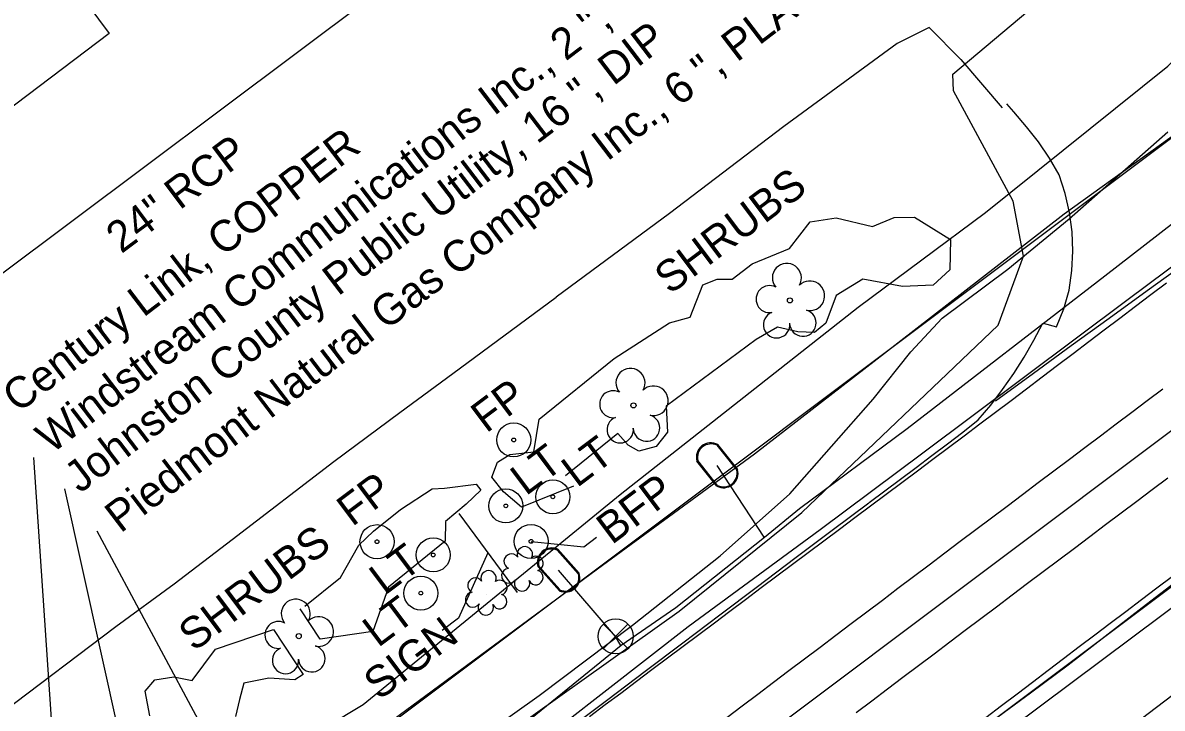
# Model space of a CAD drawing. Extents: x 2186615 to 2188822, y 629899 to 631820.
# Drawn here: x 2188283 to 2188429.1, y 631312.5 to 631400.3 of the extents above; entities that cross this region are included whole.
import ezdxf

# ---------------------------------------------------------------- set-up
doc = ezdxf.new("R2010")
doc.units = 0
for name, color, linetype in [('Exist Building Metal Canopy', 7, 'Continuous'), ('Exist Horizontal Alignment', 7, 'Continuous'), ('Exist Other Culture Located Object CELL', 7, 'Continuous'), ('Exist Other Culture Located Object Text', 7, 'Continuous'), ('Exist Other Culture Sign', 7, 'Continuous'), ('Exist Other Culture Sign Leader', 7, 'Continuous'), ('Exist Other Culture Sign Text', 7, 'Continuous'), ('Exist Right of Way Line', 7, 'Continuous'), ('Exist Roads EOP', 7, 'Continuous'), ('Exist Roads EOP Other', 7, 'Continuous'), ('Exist Roads EOT', 7, 'Continuous'), ('Exist Structure Minor Pipes RCP 24 Inch', 7, 'Continuous'), ('Exist Structure Minor Pipes RCP 24 Inch Text', 7, 'Continuous'), ('Exist Utilities Gas UG Line SUE LOS B', 7, 'Continuous'), ('Exist Utilities Gas UG Line SUE LOS B Leader', 7, 'Continuous'), ('Exist Utilities Gas UG Line SUE LOS B Text', 7, 'Continuous'), ('Exist Utilities Other Located Object CELL', 7, 'Continuous'), ('Exist Utilities Other Located Object Leader', 7, 'Continuous'), ('Exist Utilities Other Located Object Text', 7, 'Continuous'), ('Exist Utilities Sanitary Sewer Forced Main SUE LOS B', 7, 'Continuous'), ('Exist Utilities Telephone UG Cable SUE LOS C', 7, 'Continuous'), ('Exist Utilities Telephone UG Cable SUE LOS C Text', 7, 'Continuous'), ('Exist Utilities Telephone UG FO SUE LOS B', 7, 'Continuous'), ('Exist Utilities Telephone UG FO SUE LOS B Leader', 7, 'Continuous'), ('Exist Utilities Telephone UG FO SUE LOS B Text', 7, 'Continuous'), ('Exist Utilities Water Meter CELL', 7, 'Continuous'), ('Exist Utilities Water UG Line SUE LOS B', 7, 'Continuous'), ('Exist Utilities Water UG Line SUE LOS B Leader', 7, 'Continuous'), ('Exist Utilities Water UG Line SUE LOS B Text', 7, 'Continuous'), ('Exist Utilities Water Valve CELL', 7, 'Continuous'), ('Exist Vegetation Hedge Row', 7, 'Continuous'), ('Exist Vegetation Hedge Row Text', 7, 'Continuous'), ('Exist Vegetation Shrub CELL', 7, 'Continuous'), ('Exist Vegetation Tree CELL', 7, 'Continuous')]:
    doc.layers.add(name, color=color, linetype=linetype)

msp = doc.modelspace()

# ---------------------------------------------------------------- linework, layer by layer
at = {"layer": 'Exist Building Metal Canopy'}
msp.add_lwpolyline([(2188283.33, 631413.53), (2188294.13, 631398.96), (2188250.61, 631366.09), (2188239.7, 631380.77)], dxfattribs=at)
at = {"layer": 'Exist Horizontal Alignment'}
msp.add_line((2187136.41, 630378.11), (2188520.86, 631416.04), dxfattribs=at)
at = {"layer": 'Exist Other Culture Located Object CELL'}
for centre, radius in [((2188345.97, 631346.9), 2.18), ((2188345.97, 631346.9), 0.24), ((2188328.45, 631333.87), 2.18), ((2188328.45, 631333.87), 0.24)]:
    msp.add_circle(centre, radius, dxfattribs=at)
at = {"layer": 'Exist Other Culture Sign'}
msp.add_line((2188338.92, 631337.5), (2188346.41, 631327.34), dxfattribs=at)
at = {"layer": 'Exist Other Culture Sign Leader'}
msp.add_lwpolyline([(2188342.67, 631332.42), (2188338.9, 631324.06), (2188336.82, 631322.5)], dxfattribs=at)
at = {"layer": 'Exist Right of Way Line'}
msp.add_line((2187118.41, 630402.11), (2188502.83, 631440.02), dxfattribs=at)
at = {"layer": 'Exist Roads EOP'}
msp.add_line((2188413.82, 631361.87), (2188415.52, 631361.39), dxfattribs=at)
for points in [[(2188407.73, 631351.93), (2188412.58, 631355.47), (2188417.43, 631359), (2188422.29, 631362.52), (2188427.16, 631366.03), (2188432.02, 631369.54), (2188436.84, 631373.11), (2188441.63, 631376.72), (2188446.43, 631380.33), (2188451.22, 631383.93), (2188456.02, 631387.53), (2188460.83, 631391.12), (2188465.64, 631394.71), (2188470.43, 631398.33), (2188475.18, 631402), (2188479.55, 631405.46)], [(2188415.55, 631361.39), (2188416.47, 631363.71), (2188417.16, 631366.11), (2188417.51, 631368.59), (2188417.63, 631371.08), (2188417.54, 631373.58), (2188417.21, 631376.06), (2188416.66, 631378.49), (2188415.88, 631380.85), (2188414.66, 631383.02), (2188413.25, 631385.08), (2188411.71, 631387.03), (2188410.09, 631388.92), (2188409.16, 631389.97)], [(2188391.55, 631338.9), (2188393.55, 631340.39), (2188395.55, 631341.89), (2188397.55, 631343.39), (2188399.55, 631344.9), (2188401.55, 631346.4), (2188403.53, 631347.92), (2188405.48, 631349.5), (2188407.13, 631351.37), (2188408.64, 631353.36), (2188410.08, 631355.41), (2188411.41, 631357.52), (2188412.65, 631359.69), (2188413.79, 631361.88)], [(2188281.29, 631256.01), (2188286.1, 631259.61), (2188290.9, 631263.21), (2188295.7, 631266.81), (2188300.49, 631270.41), (2188305.29, 631274.01), (2188310.09, 631277.62), (2188314.89, 631281.22), (2188319.68, 631284.82), (2188324.48, 631288.43), (2188329.28, 631292.03), (2188334.08, 631295.63), (2188338.87, 631299.24), (2188343.67, 631302.84), (2188348.47, 631306.45), (2188353.26, 631310.05), (2188358.05, 631313.67), (2188362.84, 631317.28), (2188367.63, 631320.9), (2188372.41, 631324.51), (2188377.2, 631328.13), (2188381.99, 631331.74), (2188386.8, 631335.34), (2188391.5, 631338.86)], [(2188431.29, 631329.05), (2188426.54, 631325.39), (2188421.79, 631321.72), (2188417.03, 631318.07), (2188412.22, 631314.48), (2188407.4, 631310.9)]]:
    msp.add_lwpolyline(points, dxfattribs=at)
at = {"layer": 'Exist Roads EOP Other'}
for points in [[(2188399.23, 631399.74), (2188395.12, 631397.69), (2188380.6, 631387.04), (2188365.94, 631375.92), (2188351.43, 631365.2)], [(2188399.23, 631399.74), (2188403.26, 631395.66), (2188408.58, 631389.47)], [(2188185.7, 631240.3), (2188187.96, 631243.01), (2188193.78, 631247.53), (2188201.43, 631253.2), (2188215.32, 631263.49), (2188232.85, 631276.89), (2188243.59, 631284.88), (2188251.81, 631290.7), (2188259.11, 631296.15), (2188265.42, 631301.04), (2188273.98, 631307.19), (2188280.4, 631311.98), (2188294.99, 631323), (2188302.46, 631328.46), (2188309.89, 631334.14), (2188322.91, 631344.13), (2188331.39, 631350.42), (2188338.16, 631355.42), (2188351.43, 631365.2)]]:
    msp.add_lwpolyline(points, dxfattribs=at)
at = {"layer": 'Exist Roads EOT'}
for points in [[(2188355.69, 631311.49), (2188357.69, 631312.99), (2188359.69, 631314.48), (2188361.69, 631315.98), (2188363.69, 631317.48), (2188365.69, 631318.98), (2188367.69, 631320.48), (2188369.69, 631321.98), (2188371.69, 631323.48), (2188373.69, 631324.98), (2188375.69, 631326.48), (2188377.7, 631327.98), (2188379.7, 631329.48), (2188381.7, 631330.97), (2188383.7, 631332.47), (2188385.7, 631333.97), (2188387.71, 631335.47), (2188389.71, 631336.96), (2188391.71, 631338.46), (2188393.71, 631339.96), (2188395.71, 631341.46), (2188397.71, 631342.96), (2188399.71, 631344.45), (2188401.71, 631345.95), (2188403.71, 631347.45), (2188405.71, 631348.95), (2188407.71, 631350.45), (2188409.71, 631351.96), (2188411.7, 631353.47), (2188413.7, 631354.97), (2188415.69, 631356.48), (2188417.69, 631357.99), (2188419.68, 631359.5), (2188421.67, 631361.01), (2188423.67, 631362.51), (2188425.66, 631364.02), (2188427.65, 631365.53), (2188429.65, 631367.04)], [(2188373.27, 631311.34), (2188375.26, 631312.84), (2188377.26, 631314.35), (2188379.26, 631315.86), (2188381.25, 631317.36), (2188383.25, 631318.87), (2188385.24, 631320.37), (2188387.24, 631321.88), (2188389.24, 631323.38), (2188391.23, 631324.89), (2188393.23, 631326.39), (2188395.22, 631327.9), (2188397.22, 631329.4), (2188399.21, 631330.91), (2188401.21, 631332.42), (2188403.21, 631333.92), (2188405.2, 631335.42), (2188407.2, 631336.93), (2188409.2, 631338.43), (2188411.2, 631339.93), (2188413.19, 631341.44), (2188415.19, 631342.94), (2188417.19, 631344.44), (2188419.19, 631345.95), (2188421.18, 631347.45), (2188423.18, 631348.95), (2188425.18, 631350.46), (2188427.18, 631351.96), (2188429.17, 631353.46)], [(2188389.88, 631311.99), (2188391.87, 631313.49), (2188393.87, 631315), (2188395.86, 631316.51), (2188397.86, 631318.01), (2188399.86, 631319.52), (2188401.85, 631321.02), (2188403.85, 631322.53), (2188405.85, 631324.03), (2188407.84, 631325.53), (2188409.84, 631327.04), (2188411.84, 631328.54), (2188413.84, 631330.04), (2188415.83, 631331.55), (2188417.83, 631333.05), (2188419.83, 631334.55), (2188421.83, 631336.06), (2188423.82, 631337.56), (2188425.82, 631339.06), (2188427.82, 631340.57), (2188429.82, 631342.07)], [(2188430.42, 631329.42), (2188428.42, 631327.91), (2188426.43, 631326.41), (2188424.43, 631324.9), (2188422.43, 631323.39), (2188420.44, 631321.89), (2188418.45, 631320.38), (2188416.45, 631318.87), (2188414.46, 631317.36), (2188412.47, 631315.85), (2188410.48, 631314.34), (2188408.48, 631312.83), (2188406.49, 631311.32)]]:
    msp.add_lwpolyline(points, dxfattribs=at)
at = {"layer": 'Exist Structure Minor Pipes RCP 24 Inch'}
msp.add_line((2188121.59, 631249.35), (2188427.77, 631478.57), dxfattribs=at)
at = {"layer": 'Exist Utilities Gas UG Line SUE LOS B'}
msp.add_lwpolyline([(2188219.39, 631219.84), (2188231.62, 631228.2), (2188246.17, 631238.93), (2188255.42, 631245.33), (2188268.48, 631254.78), (2188278.59, 631262.16), (2188293.89, 631272.96), (2188309.4, 631283.84), (2188325.21, 631295.95), (2188338.4, 631306.43), (2188349.22, 631314.15), (2188361.2, 631323.18), (2188372.45, 631332.07), (2188381.36, 631339.98), (2188392.05, 631352.12), (2188396.89, 631358.2), (2188400.9, 631362.5), (2188409.32, 631368.76), (2188417.18, 631375.21), (2188429.81, 631386.38)], dxfattribs=at)
at = {"layer": 'Exist Utilities Gas UG Line SUE LOS B Leader'}
msp.add_line((2188316.89, 631289.98), (2188292.6, 631335.2), dxfattribs=at)
at = {"layer": 'Exist Utilities Other Located Object CELL'}
for centre, radius in [((2188350.99, 631339.62), 2.18), ((2188344.96, 631338.45), 2.18), ((2188350.99, 631339.62), 0.24), ((2188344.96, 631338.45), 0.24), ((2188348.19, 631333.91), 2.18), ((2188335.66, 631332.17), 2.18), ((2188348.19, 631333.91), 0.24), ((2188335.66, 631332.17), 0.24), ((2188334.07, 631327.28), 2.18), ((2188334.07, 631327.28), 0.24)]:
    msp.add_circle(centre, radius, dxfattribs=at)
at = {"layer": 'Exist Utilities Other Located Object Leader'}
msp.add_lwpolyline([(2188348.19, 631333.91), (2188354.95, 631333.21), (2188356.57, 631334.43)], dxfattribs=at)
at = {"layer": 'Exist Utilities Sanitary Sewer Forced Main SUE LOS B'}
msp.add_lwpolyline([(2188052.08, 631035.89), (2188074.5, 631052.61), (2188093.79, 631066.37), (2188121.43, 631086.62), (2188146.17, 631105.29), (2188183, 631130.32), (2188212.25, 631151.9), (2188236.06, 631169.55), (2188274.9, 631197.79), (2188300.59, 631215.98), (2188344.72, 631249.04), (2188387.13, 631281.33), (2188437.44, 631319.58), (2188480.75, 631351.94), (2188530.77, 631388.8), (2188537.37, 631394.07)], dxfattribs=at)
at = {"layer": 'Exist Utilities Telephone UG Cable SUE LOS C'}
for points in [[(2188408.07, 631361.6), (2188411.32, 631370.46), (2188409.98, 631377.49), (2188402.34, 631391.62), (2188402.24, 631393.77), (2188411.88, 631401.83), (2188434.34, 631422.63), (2188440.61, 631427.17), (2188442.76, 631427.28), (2188447.4, 631424.9), (2188452.58, 631419.05), (2188455.8, 631415.11), (2188458.95, 631413.82), (2188466.14, 631418.76)], [(2188359.63, 631339.91), (2188390.14, 631363.91), (2188406.42, 631376.04), (2188429.82, 631394.77), (2188450.5, 631414.66)], [(2188096.88, 630993.34), (2188080.22, 631017.51), (2188064.37, 631042.87), (2188062.98, 631045.24), (2188062.65, 631047.71), (2188067.09, 631054.3), (2188068.63, 631056.84), (2188089.09, 631072.74), (2188116.44, 631092.81), (2188141.03, 631110.94), (2188178.22, 631138.01), (2188229.96, 631175.9), (2188269.4, 631205.59), (2188294.58, 631224.2), (2188340.11, 631258.2), (2188382.72, 631289.85), (2188432.93, 631327.36), (2188477.32, 631360.56), (2188524.82, 631398.08), (2188530.94, 631402.62)], [(2188239.88, 631089.23), (2188209.7, 631139.17), (2188205.31, 631145.33), (2188202.92, 631147.6), (2188200.81, 631153.01), (2188202.37, 631156.1), (2188209.69, 631162.82), (2188228.85, 631177.06), (2188268.68, 631206.68), (2188293.54, 631225.66), (2188339.11, 631259.48), (2188381.57, 631291.6), (2188431.82, 631329.3), (2188475.74, 631362.76), (2188523.99, 631399.21), (2188530.06, 631403.8)], [(2188312.37, 631280.51), (2188341.87, 631302.43), (2188368.35, 631323.01), (2188385.25, 631335.41), (2188398.42, 631345.26), (2188424.55, 631364.83), (2188476.35, 631403.47)], [(2188310.34, 631283.34), (2188339.41, 631305.19), (2188367.17, 631324.97), (2188382.91, 631337.59), (2188408.07, 631361.6)], [(2188214.19, 631233.71), (2188214.21, 631236.64), (2188215.1, 631239.68), (2188225.32, 631247.53), (2188241.06, 631256.41), (2188259.35, 631266.95), (2188283.55, 631284.49), (2188303.17, 631298.86), (2188326.67, 631313), (2188359.63, 631339.91)]]:
    msp.add_lwpolyline(points, dxfattribs=at)
at = {"layer": 'Exist Utilities Telephone UG FO SUE LOS B'}
msp.add_lwpolyline([(2188303.07, 631290.83), (2188335.53, 631314.77), (2188356.73, 631330.39), (2188376.84, 631345.11), (2188395.22, 631359.35), (2188416.54, 631375.89), (2188457.16, 631405.12)], dxfattribs=at)
at = {"layer": 'Exist Utilities Telephone UG FO SUE LOS B Leader'}
msp.add_line((2188288.8, 631280.26), (2188284.46, 631344.66), dxfattribs=at)
at = {"layer": 'Exist Utilities Water Meter CELL'}
for p, q in [((2188372.06, 631343.65), (2188372.06, 631343.65)), ((2188351.73, 631330.24), (2188351.73, 631330.24))]:
    msp.add_line(p, q, dxfattribs=at)
for points in [[(2188372.01, 631346.22), (2188374.55, 631343.03)], [(2188372.11, 631346.3), (2188374.66, 631343.12)], [(2188372, 631341), (2188369.44, 631344.2)], [(2188372.11, 631341.08), (2188369.55, 631344.29)], [(2188351.54, 631332.8), (2188354.25, 631329.76)], [(2188351.64, 631332.89), (2188354.35, 631329.85)], [(2188351.82, 631327.59), (2188349.09, 631330.65)], [(2188351.92, 631327.68), (2188349.19, 631330.74)]]:
    msp.add_lwpolyline(points, dxfattribs=at)
for centre, radius, start, end in [((2188371.24, 631344.67), 1.86, 61.8182, 194.6196), ((2188371.25, 631344.66), 1.73, 63.9411, 192.4226), ((2188372.87, 631342.64), 1.86, 242.2885, 14.9486), ((2188372.87, 631342.63), 1.73, 243.7674, 13.513), ((2188350.85, 631331.21), 1.86, 64.9405, 197.7419), ((2188350.86, 631331.2), 1.73, 67.0634, 195.5449), ((2188352.59, 631329.28), 1.86, 245.4108, 18.0709), ((2188352.6, 631329.27), 1.73, 246.8897, 16.6353)]:
    msp.add_arc(centre, radius, start, end, dxfattribs=at)
at = {"layer": 'Exist Utilities Water UG Line SUE LOS B'}
msp.add_line((2188378.09, 631334.43), (2188372.06, 631343.65), dxfattribs=at)
for points in [[(2188311.2, 631281.93), (2188339.94, 631304.52), (2188359.74, 631320.63), (2188366.75, 631325.42), (2188378.12, 631334.45), (2188382.61, 631338.14), (2188396.4, 631348.39), (2188421.73, 631367.94), (2188462.18, 631399.29)], [(2188359.7, 631320.59), (2188359.03, 631321.73), (2188351.73, 631330.24)]]:
    msp.add_lwpolyline(points, dxfattribs=at)
at = {"layer": 'Exist Utilities Water UG Line SUE LOS B Leader'}
msp.add_line((2188302.8, 631275.85), (2188288.43, 631340.62), dxfattribs=at)
at = {"layer": 'Exist Utilities Water Valve CELL'}
msp.add_lwpolyline([(2188360.61, 631323.32), (2188357.46, 631320.17), (2188359.04, 631321.74), (2188360.61, 631320.17), (2188357.46, 631323.32)], dxfattribs=at)
msp.add_circle((2188359.04, 631321.74), 2.23, dxfattribs=at)
at = {"layer": 'Exist Vegetation Hedge Row'}
for points in [[(2188349.25, 631349.58), (2188358.83, 631357.34), (2188365.94, 631361.9), (2188368.58, 631362.62), (2188370.21, 631366.78), (2188372.03, 631367.49), (2188373.99, 631367.5), (2188376.52, 631369.45), (2188381.34, 631371.41), (2188383.97, 631374.83), (2188387.31, 631375.37), (2188391.95, 631374.26), (2188394.74, 631375.39), (2188397.32, 631375.44), (2188401.97, 631372.58), (2188401.88, 631368.69), (2188399.75, 631366.75), (2188395.8, 631366.55), (2188390.74, 631367.5), (2188387.29, 631365.39), (2188385.96, 631361.85), (2188384.51, 631360.67), (2188382.37, 631360.75), (2188379.77, 631361.37), (2188377.06, 631359.77), (2188365.5, 631351.24), (2188365.7, 631347.92), (2188364.24, 631346.05), (2188362.02, 631345.47), (2188360.63, 631346.22), (2188359.3, 631347.72), (2188352.59, 631342.29)], [(2188353.64, 631340.99), (2188346.95, 631338.28), (2188344.65, 631340.25), (2188343.18, 631342.15), (2188343.91, 631344.04), (2188345.48, 631345.04), (2188348.57, 631345.4), (2188349.25, 631349.58)], [(2188319.21, 631325.62), (2188323.76, 631329.29), (2188326.12, 631333.42), (2188328.01, 631335.21), (2188331.48, 631338.01), (2188335.5, 631340.62), (2188337.09, 631340.71), (2188341.14, 631341.25), (2188341.75, 631340.48), (2188339.88, 631338.67), (2188337.21, 631336.47), (2188337.17, 631333.95), (2188329.93, 631328.05), (2188327.9, 631322.38), (2188321.18, 631321.38), (2188318.62, 631325.26)], [(2188299.34, 631311.54), (2188298.74, 631314.71), (2188299.98, 631316.17), (2188302.39, 631316.54), (2188304.75, 631316.09), (2188307.77, 631320.09), (2188315.17, 631322.61), (2188318.98, 631316.86), (2188317.93, 631316.15), (2188314.58, 631316.39), (2188311.4, 631315.76), (2188310.84, 631313.66), (2188310.32, 631311.46)]]:
    msp.add_lwpolyline(points, dxfattribs=at)
at = {"layer": 'Exist Vegetation Shrub CELL'}
for p, q in [((2188347.17, 631330.21), (2188347.17, 631330.21)), ((2188342.52, 631327.13), (2188342.52, 631327.13))]:
    msp.add_line(p, q, dxfattribs=at)
for centre, radius, start, end in [((2188347.4, 631332.25), 0.99, 334.8391, 200.4717), ((2188345.69, 631331.34), 0.968, 35.8908, 245.4216), ((2188348.84, 631331.08), 0.929, 284.4567, 126.0861), ((2188342.75, 631329.17), 0.99, 334.8391, 200.4717), ((2188345.37, 631329.5), 0.955, 95.1099, 327.9534), ((2188348.8, 631329.28), 0.937, 204.9913, 73.4601), ((2188341.04, 631328.26), 0.968, 35.8908, 245.4216), ((2188344.2, 631328), 0.929, 284.4567, 126.0861), ((2188347.04, 631328.52), 0.984, 151.2797, 21.387), ((2188340.72, 631326.43), 0.955, 95.1099, 327.9534), ((2188344.16, 631326.2), 0.937, 204.9913, 73.4601), ((2188342.4, 631325.45), 0.984, 151.2797, 21.387)]:
    msp.add_arc(centre, radius, start, end, dxfattribs=at)
at = {"layer": 'Exist Vegetation Tree CELL'}
for p, q in [((2188381.37, 631364.78), (2188381.37, 631364.78)), ((2188361.32, 631351.33), (2188361.32, 631351.33)), ((2188318.42, 631321.77), (2188318.42, 631321.77))]:
    msp.add_line(p, q, dxfattribs=at)
for centre in [(2188381.37, 631364.78), (2188361.32, 631351.33), (2188318.42, 631321.77)]:
    msp.add_circle(centre, 0.326, dxfattribs=at)
for centre, radius, start, end in [((2188380.98, 631367.66), 1.86, 330.1651, 219.7134), ((2188378.76, 631364.94), 1.73, 62.6636, 279.3457), ((2188383.92, 631365.37), 1.9, 257.1011, 134.1999), ((2188379.67, 631361.66), 1.69, 111.5671, 6.231), ((2188383.04, 631361.88), 1.7, 181.2822, 74.56), ((2188360.94, 631354.2), 1.86, 330.1651, 219.7134), ((2188358.72, 631351.48), 1.73, 62.6636, 279.3457), ((2188363.87, 631351.92), 1.9, 257.1011, 134.1999), ((2188363, 631348.43), 1.7, 181.2822, 74.56), ((2188359.62, 631348.21), 1.69, 111.5671, 6.231), ((2188318.04, 631324.64), 1.86, 330.1651, 219.7134), ((2188320.97, 631322.35), 1.9, 257.1011, 134.1999), ((2188315.82, 631321.92), 1.73, 62.6636, 279.3457), ((2188316.72, 631318.65), 1.69, 111.5671, 6.231), ((2188320.1, 631318.87), 1.7, 181.2822, 74.56)]:
    msp.add_arc(centre, radius, start, end, dxfattribs=at)

# ---------------------------------------------------------------- texts
at = {"layer": 'Exist Other Culture Located Object Text'}
for p in [(2188342.46, 631347.69), (2188325.27, 631335.72)]:
    msp.add_text('FP', height=4, rotation=36.8593, dxfattribs=at).set_placement(p)
at = {"layer": 'Exist Other Culture Sign Text'}
msp.add_text('SIGN', height=4, rotation=36.8593, dxfattribs=at).set_placement((2188328.71, 631313.46))
at = {"layer": 'Exist Structure Minor Pipes RCP 24 Inch Text'}
msp.add_text('24" RCP', height=4, rotation=36.8196, dxfattribs=at).set_placement((2188295.68, 631370.69))
at = {"layer": 'Exist Utilities Gas UG Line SUE LOS B Text'}
msp.add_text('Piedmont Natural Gas Company Inc., 6 ", PLASTIC', height=4, rotation=37.3672, dxfattribs=at).set_placement((2188295.57, 631334.88))
at = {"layer": 'Exist Utilities Other Located Object Text'}
for s, p in [('LT', (2188354.07, 631340.71)), ('LT', (2188347.53, 631339.66)), ('BFP', (2188358.54, 631333.4)), ('LT', (2188329.44, 631326.92)), ('LT', (2188328.58, 631320.22))]:
    msp.add_text(s, height=4, rotation=36.8593, dxfattribs=at).set_placement(p)
at = {"layer": 'Exist Utilities Telephone UG Cable SUE LOS C Text'}
msp.add_text('Century Link, COPPER', height=4, rotation=37.3672, dxfattribs=at).set_placement((2188282.44, 631350.26))
at = {"layer": 'Exist Utilities Telephone UG FO SUE LOS B Text'}
msp.add_text('Windstream Communications Inc., 2 ", CONDUIT', height=4, rotation=37.3672, dxfattribs=at).set_placement((2188286.72, 631345.03))
at = {"layer": 'Exist Utilities Water UG Line SUE LOS B Text'}
msp.add_text('Johnston County Public Utility, 16 ", DIP', height=4, rotation=37.3672, dxfattribs=at).set_placement((2188290.37, 631339.98))
at = {"layer": 'Exist Vegetation Hedge Row Text'}
for p in [(2188365.98, 631365.44), (2188304.98, 631319.7)]:
    msp.add_text('SHRUBS', height=4, rotation=36.8593, dxfattribs=at).set_placement(p)

doc.saveas('drawing.dxf')
